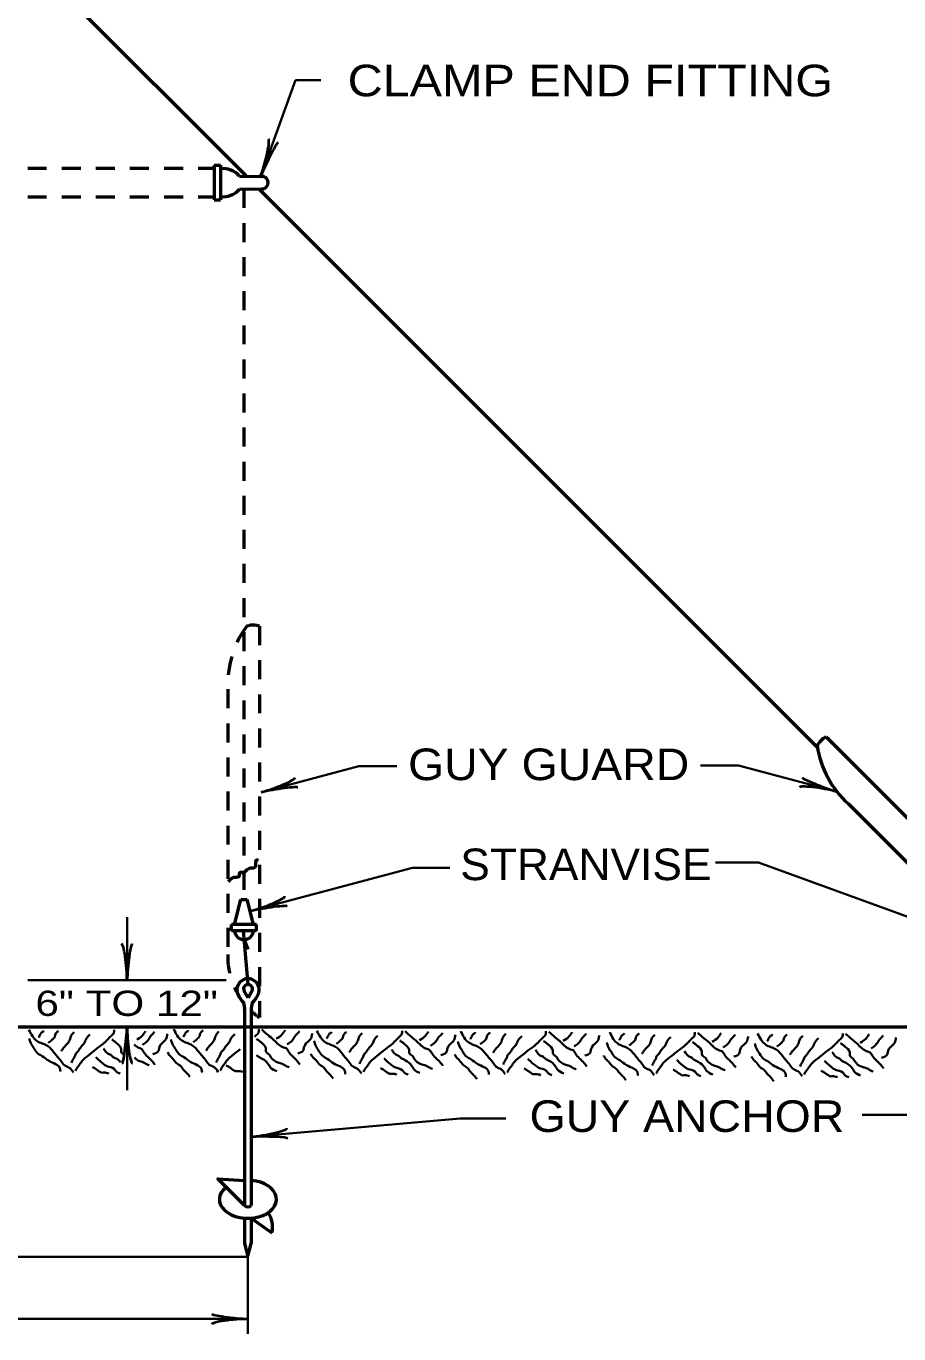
# Model space of a CAD drawing. Extents: x 12366 to 13046, y 9129 to 9570.
# Drawn here: x 12793.4 to 12862.5, y 9373.5 to 9477.1 of the extents above; entities that cross this region are included whole.
import ezdxf
from ezdxf.enums import TextEntityAlignment as Align

# ---------------------------------------------------------------- set-up
doc = ezdxf.new("R2010")
doc.units = 0
doc.linetypes.add('SHORT_DASHED', pattern=[2.7, 1.5, -1.2])
doc.layers.add('1', color=7, linetype='Continuous', lineweight=53)

msp = doc.modelspace()

# ---------------------------------------------------------------- linework, layer by layer
at = {"layer": '1'}
for p, q in [((12749.576, 9526.413), (12810.747, 9465.242)), ((12808.241, 9466.052), (12808.241, 9463.303)), ((12808.241, 9466.052), (12808.741, 9466.052)), ((12808.741, 9466.052), (12808.741, 9463.303)), ((12810.253, 9465.181), (12811.991, 9465.177)), ((12810.253, 9464.17), (12812.069, 9464.177)), ((12811.799, 9464.19), (12856.023, 9419.966)), ((12808.241, 9463.303), (12808.741, 9463.303)), ((12856.715, 9420.771), (12878.635, 9398.851)), ((12858.482, 9415.468), (12873.332, 9400.618)), ((12809.862, 9405.911), (12810.362, 9407.911)), ((12810.362, 9407.911), (12810.862, 9407.911)), ((12811.362, 9405.911), (12810.862, 9407.911)), ((12811.612, 9405.911), (12809.612, 9405.911)), ((12809.612, 9405.411), (12809.612, 9405.911)), ((12811.612, 9405.411), (12811.612, 9405.911)), ((12811.612, 9405.411), (12809.612, 9405.411)), ((12810.94, 9401.156), (12810.568, 9405.408)), ((12810.627, 9404.725), (12810.906, 9403.961)), ((12810.932, 9400.107), (12810.632, 9400.626)), ((12810.932, 9400.107), (12811.232, 9400.626)), ((12811.189, 9399.121), (12811.189, 9393.883)), ((12722.941, 9397.801), (12909.771, 9397.801)), ((12811.189, 9393.841), (12811.189, 9383.648)), ((12811.189, 9382.648), (12811.189, 9380.648)), ((12811.189, 9382.648), (12812.828, 9381.501))]:
    msp.add_line(p, q, dxfattribs=at)
at = {"layer": '1', "linetype": 'SHORT_DASHED'}
for p, q in [((12747.583, 9465.812), (12808.241, 9465.812)), ((12810.612, 9464.172), (12810.612, 9407.911)), ((12747.584, 9463.563), (12808.241, 9463.563)), ((12811.835, 9429.545), (12811.835, 9398.545)), ((12809.335, 9424.545), (12809.335, 9403.545))]:
    msp.add_line(p, q, dxfattribs=at)
at = {"layer": '1', "lineweight": 35}
for p, q in [((12819.718, 9418.465), (12811.99, 9416.394)), ((12819.718, 9418.465), (12822.718, 9418.465)), ((12849.776, 9418.521), (12846.776, 9418.521)), ((12857.504, 9416.451), (12849.776, 9418.521)), ((12823.949, 9410.414), (12811.165, 9406.989)), ((12823.949, 9410.414), (12826.928, 9410.414)), ((12851.357, 9410.834), (12847.966, 9410.834)), ((12871.535, 9403.49), (12851.357, 9410.834)), ((12801.351, 9401.504), (12801.351, 9406.504)), ((12809.21, 9401.504), (12793.491, 9401.504)), ((12801.351, 9397.801), (12801.351, 9392.801)), ((12827.73, 9390.549), (12811.189, 9389.102)), ((12827.73, 9390.549), (12831.352, 9390.549)), ((12863.862, 9390.849), (12859.568, 9390.849)), ((12810.907, 9379.6), (12791.754, 9379.6)), ((12810.922, 9379.562), (12810.922, 9373.495)), ((12747.004, 9374.68), (12810.943, 9374.68))]:
    msp.add_line(p, q, dxfattribs=at)
msp.add_lwpolyline([(12811.966, 9465.264), (12814.702, 9472.782), (12816.702, 9472.782)], dxfattribs=at)
at = {"layer": '1'}
for points in [[(12810.666, 9399.121), (12810.666, 9393.841), (12810.666, 9383.648)], [(12810.666, 9383.648), (12808.545, 9385.769), (12810.653, 9385.637)], [(12810.666, 9382.648), (12810.666, 9380.648), (12810.928, 9379.648), (12811.189, 9380.648)]]:
    msp.add_lwpolyline(points, dxfattribs=at)
for centre, radius, start, end in [((12808.958, 9464.097), 1.689, 39.94521, 97.50756), ((12812.03, 9464.677), 0.501, 265.53287, 94.46714), ((12808.958, 9465.255), 1.689, 262.49244, 320.05479), ((12857.397, 9419.381), 1.548, 116.15616, 153.84384), ((12863.657, 9421.219), 7.737, 188.58388, 228.01714), ((12810.612, 9405.479), 0.753, 185.20411, 354.79589), ((12810.933, 9400.734), 0.887, 337.37581, 202.62419), ((12810.932, 9400.807), 0.35, 328.9871, 211.0129), ((12812.574, 9401.633), 2.755, 206.74116, 223.96028), ((12809.203, 9399.242), 1.469, 355.24577, 19.00426), ((12812.653, 9399.242), 1.469, 160.99574, 184.75423), ((12809.675, 9401.384), 2.301, 313.69833, 334.49446), ((12810.928, 9383.929), 0.384, 227.04039, 312.95961), ((12810.789, 9381.953), 2.088, 347.48706, 33.42981)]:
    msp.add_arc(centre, radius, start, end, dxfattribs=at)
at = {"layer": '1', "linetype": 'SHORT_DASHED'}
for centre, radius, start, end in [((12817.061, 9424.952), 7.737, 143.58388, 183.01714), ((12811.335, 9428.08), 1.548, 71.15616, 108.84384), ((12815.16, 9403.333), 5.829, 177.90975, 209.56823), ((12815.16, 9403.333), 5.829, 227.0576, 235.22035)]:
    msp.add_arc(centre, radius, start, end, dxfattribs=at)
at = {"layer": '1', "lineweight": 40}
for centre, major_axis, ratio, start_param, end_param in [((12812.08, 9466.384), (-0.464, -1.731), 0.122415, 0.8963533, 3.1415927), ((12812.548, 9466.245), (0.766, 1.59), 0.07063, 6.2823074, 8.5597026), ((12812.973, 9416.943), (-1.684, -0.613), 0.122415, 0.8963533, 3.1415927), ((12856.476, 9416.945), (-1.651, 0.624), 0.07063, 6.2823074, 8.5597026), ((12813.127, 9416.48), (1.742, 0.285), 0.07063, 6.2823074, 8.5597026), ((12856.378, 9416.466), (1.765, -0.311), 0.122415, 0.8963533, 3.1415927), ((12812.148, 9407.538), (-1.684, -0.613), 0.122415, 0.8963533, 3.1415927), ((12812.302, 9407.074), (1.742, 0.285), 0.07063, 6.2823074, 8.5597026), ((12801.074, 9402.595), (0.156, -1.786), 0.122415, 0.8963533, 3.1415927), ((12801.562, 9402.625), (0.176, 1.756), 0.07063, 6.2823074, 8.5597026), ((12801.139, 9396.681), (-0.176, -1.756), 0.07063, 6.2823074, 8.5597026), ((12801.627, 9396.71), (-0.156, 1.786), 0.122415, 0.8963533, 3.1415927), ((12812.252, 9389.472), (-1.765, -0.311), 0.122415, 0.8963533, 3.1415927), ((12812.324, 9388.989), (1.765, -0.022), 0.07063, 6.2823074, 8.5597026), ((12809.823, 9374.891), (1.756, -0.176), 0.07063, 3.1407148, 5.41811), ((12809.852, 9374.403), (1.786, 0.156), 0.122415, 0.8963533, 3.1415927)]:
    msp.add_ellipse(centre, major_axis=major_axis, ratio=ratio, start_param=start_param, end_param=end_param, dxfattribs=at)
at = {"layer": '1'}
msp.add_ellipse((12810.928, 9384.148), major_axis=(-2.262, 0), ratio=0.663245, start_param=5.5824837, end_param=10.8796755, dxfattribs=at)
msp.add_spline([(12811.769, 9411), (12811.601, 9411.015), (12811.535, 9410.642), (12811.493, 9410.449), (12811.146, 9410.37), (12810.765, 9410.178), (12810.605, 9410.029), (12810.251, 9409.995), (12810.228, 9409.74), (12809.893, 9409.643), (12809.601, 9409.539), (12809.365, 9409.29)], degree=3, dxfattribs=at)
at = {"layer": '1', "lineweight": 35}
for points in [[(12793.581, 9397.583), (12794.221, 9396.688), (12795.053, 9396.304), (12795.564, 9395.792), (12795.82, 9395.472), (12796.14, 9395.088), (12796.396, 9394.768), (12796.78, 9394.576), (12797.1, 9394.192)], [(12800.331, 9397.583), (12800.331, 9397.456), (12800.267, 9397.263), (12800.139, 9397.136), (12800.011, 9397.008), (12799.755, 9396.752), (12799.563, 9396.56), (12798.987, 9396.112), (12798.667, 9395.856), (12798.027, 9395.344), (12797.771, 9395.088), (12797.644, 9394.896), (12797.452, 9394.64), (12797.26, 9394.32)], [(12805.049, 9397.625), (12805.689, 9396.729), (12806.521, 9396.345), (12807.032, 9395.833), (12807.288, 9395.513), (12807.608, 9395.129), (12807.864, 9394.81), (12808.248, 9394.618), (12808.568, 9394.234)], [(12811.799, 9397.625), (12811.799, 9397.497), (12811.735, 9397.305), (12811.607, 9397.177), (12811.479, 9397.049), (12811.459, 9397.029)], [(12812.023, 9397.593), (12812.534, 9397.145), (12812.982, 9396.761), (12813.75, 9396.185), (12813.942, 9396.121), (12814.134, 9395.865), (12814.454, 9395.481), (12814.838, 9395.097), (12815.03, 9394.842)], [(12793.605, 9396.9), (12793.733, 9396.516), (12793.988, 9396.1), (12794.308, 9395.684), (12794.628, 9395.492), (12795.172, 9395.108), (12796.036, 9394.532), (12796.068, 9394.277)], [(12794.733, 9397.512), (12794.637, 9397.384), (12794.605, 9397.384), (12794.541, 9397.32), (12794.381, 9397.032), (12794.349, 9396.968)], [(12795.916, 9397.48), (12795.724, 9397.32), (12795.66, 9397.16), (12795.596, 9396.968), (12795.468, 9396.84), (12795.404, 9396.776), (12795.116, 9396.552)], [(12797.164, 9397.384), (12796.972, 9397.192), (12796.844, 9396.872), (12796.684, 9396.552), (12796.332, 9396.168), (12796.204, 9395.976), (12796.14, 9395.88)], [(12798.411, 9397.192), (12798.123, 9396.872), (12797.963, 9396.52), (12797.708, 9396.232), (12797.516, 9395.944), (12797.324, 9395.72), (12797.228, 9395.496), (12797.1, 9395.272), (12796.94, 9394.953)], [(12800.139, 9396.808), (12800.331, 9396.68), (12800.523, 9396.52), (12800.874, 9396.072), (12800.906, 9395.784), (12801.081, 9395.632)], [(12802.119, 9396.799), (12802.567, 9397.119), (12802.663, 9397.246), (12802.823, 9397.47)], [(12802.57, 9396.392), (12802.922, 9396.648), (12803.146, 9396.968), (12803.21, 9397.064), (12803.338, 9397.192), (12803.53, 9397.416)], [(12803.402, 9395.656), (12803.85, 9395.912), (12803.913, 9396.2), (12804.329, 9396.712), (12804.457, 9396.872), (12804.521, 9397.128), (12804.553, 9397.256)], [(12804.825, 9396.817), (12804.953, 9396.433), (12805.209, 9396.017), (12805.529, 9395.602), (12805.849, 9395.41), (12806.392, 9395.026), (12807.256, 9394.45), (12807.288, 9394.194)], [(12806.201, 9397.553), (12806.105, 9397.425), (12806.073, 9397.425), (12806.009, 9397.361), (12805.849, 9397.073), (12805.817, 9397.009)], [(12807.384, 9397.521), (12807.192, 9397.361), (12807.128, 9397.201), (12807.064, 9397.009), (12806.936, 9396.881), (12806.872, 9396.817), (12806.584, 9396.593)], [(12808.632, 9397.425), (12808.44, 9397.233), (12808.312, 9396.913), (12808.152, 9396.593), (12807.8, 9396.209), (12807.672, 9396.017), (12807.608, 9395.922)], [(12809.879, 9397.233), (12809.591, 9396.913), (12809.431, 9396.561), (12809.176, 9396.273), (12808.984, 9395.985), (12808.792, 9395.762), (12808.696, 9395.538), (12808.568, 9395.314), (12808.408, 9394.994)], [(12811.607, 9396.849), (12811.799, 9396.721), (12811.991, 9396.561), (12812.342, 9396.113), (12812.374, 9395.826), (12812.63, 9395.602), (12812.726, 9395.442), (12813.366, 9394.962), (12813.75, 9394.834), (12813.846, 9394.77), (12814.198, 9394.61)], [(12813.174, 9396.881), (12813.622, 9397.201), (12813.718, 9397.329), (12813.878, 9397.553)], [(12814.038, 9396.433), (12814.39, 9396.689), (12814.614, 9397.009), (12814.678, 9397.105), (12814.806, 9397.233), (12814.998, 9397.457)], [(12814.87, 9395.698), (12815.317, 9395.953), (12815.381, 9396.241), (12815.797, 9396.753), (12815.925, 9396.913), (12815.989, 9397.169), (12816.021, 9397.297)], [(12816.169, 9396.693), (12816.297, 9396.31), (12816.553, 9395.894), (12816.873, 9395.478), (12817.193, 9395.286), (12817.737, 9394.902), (12818.601, 9394.326), (12818.632, 9394.07)], [(12816.393, 9397.501), (12817.033, 9396.605), (12817.865, 9396.221), (12818.377, 9395.709), (12818.632, 9395.39), (12818.952, 9395.006), (12819.208, 9394.686), (12819.592, 9394.494), (12819.912, 9394.11)], [(12817.545, 9397.429), (12817.449, 9397.301), (12817.417, 9397.301), (12817.353, 9397.237), (12817.193, 9396.949), (12817.161, 9396.885)], [(12818.728, 9397.397), (12818.537, 9397.237), (12818.472, 9397.077), (12818.408, 9396.885), (12818.281, 9396.757), (12818.217, 9396.693), (12817.929, 9396.469)], [(12819.976, 9397.301), (12819.784, 9397.109), (12819.656, 9396.789), (12819.496, 9396.47), (12819.144, 9396.086), (12819.016, 9395.894), (12818.952, 9395.798)], [(12821.224, 9397.109), (12820.936, 9396.789), (12820.776, 9396.438), (12820.52, 9396.15), (12820.328, 9395.862), (12820.136, 9395.638), (12820.04, 9395.414), (12819.912, 9395.19), (12819.752, 9394.87)], [(12823.143, 9397.501), (12823.143, 9397.373), (12823.079, 9397.181), (12822.951, 9397.053), (12822.823, 9396.925), (12822.567, 9396.669), (12822.375, 9396.477), (12821.799, 9396.029), (12821.479, 9395.773), (12820.84, 9395.262), (12820.584, 9395.006), (12820.456, 9394.814), (12820.264, 9394.558), (12820.072, 9394.238)], [(12822.951, 9396.725), (12823.143, 9396.597), (12823.335, 9396.438), (12823.687, 9395.99), (12823.719, 9395.702), (12823.975, 9395.478), (12824.071, 9395.318), (12824.71, 9394.838), (12825.094, 9394.71), (12825.19, 9394.646), (12825.542, 9394.486)], [(12823.367, 9397.469), (12823.879, 9397.021), (12824.326, 9396.637), (12825.094, 9396.061), (12825.286, 9395.997), (12825.478, 9395.742), (12825.798, 9395.358), (12826.182, 9394.974), (12826.374, 9394.718)], [(12824.519, 9396.757), (12824.966, 9397.077), (12825.062, 9397.205), (12825.222, 9397.429)], [(12825.382, 9396.31), (12825.734, 9396.565), (12825.958, 9396.885), (12826.022, 9396.981), (12826.15, 9397.109), (12826.342, 9397.333)], [(12826.214, 9395.574), (12826.662, 9395.83), (12826.726, 9396.118), (12827.142, 9396.629), (12827.27, 9396.789), (12827.333, 9397.045), (12827.365, 9397.173)], [(12827.555, 9396.652), (12827.683, 9396.268), (12827.939, 9395.852), (12828.259, 9395.437), (12828.578, 9395.245), (12829.122, 9394.861), (12829.986, 9394.285), (12830.018, 9394.029)], [(12827.779, 9397.46), (12828.419, 9396.564), (12829.25, 9396.18), (12829.762, 9395.668), (12830.018, 9395.348), (12830.338, 9394.965), (12830.594, 9394.645), (12830.978, 9394.453), (12831.298, 9394.069)], [(12828.93, 9397.388), (12828.834, 9397.26), (12828.802, 9397.26), (12828.738, 9397.196), (12828.578, 9396.908), (12828.547, 9396.844)], [(12830.114, 9397.356), (12829.922, 9397.196), (12829.858, 9397.036), (12829.794, 9396.844), (12829.666, 9396.716), (12829.602, 9396.652), (12829.314, 9396.428)], [(12831.361, 9397.26), (12831.17, 9397.068), (12831.042, 9396.748), (12830.882, 9396.428), (12830.53, 9396.044), (12830.402, 9395.852), (12830.338, 9395.757)], [(12832.609, 9397.068), (12832.321, 9396.748), (12832.161, 9396.396), (12831.905, 9396.108), (12831.713, 9395.82), (12831.521, 9395.597), (12831.425, 9395.373), (12831.297, 9395.149), (12831.138, 9394.829)], [(12834.528, 9397.46), (12834.528, 9397.332), (12834.464, 9397.14), (12834.336, 9397.012), (12834.208, 9396.884), (12833.953, 9396.628), (12833.761, 9396.436), (12833.185, 9395.988), (12832.865, 9395.732), (12832.225, 9395.22), (12831.969, 9394.965), (12831.841, 9394.773), (12831.649, 9394.517), (12831.458, 9394.197)], [(12834.336, 9396.684), (12834.528, 9396.556), (12834.72, 9396.396), (12835.072, 9395.948), (12835.104, 9395.661), (12835.36, 9395.437), (12835.456, 9395.277), (12836.096, 9394.797), (12836.48, 9394.669), (12836.576, 9394.605), (12836.928, 9394.445)], [(12834.752, 9397.428), (12835.264, 9396.98), (12835.712, 9396.596), (12836.48, 9396.02), (12836.672, 9395.956), (12836.864, 9395.7), (12837.183, 9395.316), (12837.567, 9394.932), (12837.759, 9394.677)], [(12835.904, 9396.716), (12836.352, 9397.036), (12836.448, 9397.164), (12836.608, 9397.388)], [(12836.768, 9396.268), (12837.12, 9396.524), (12837.343, 9396.844), (12837.407, 9396.94), (12837.535, 9397.068), (12837.727, 9397.292)], [(12837.599, 9395.533), (12838.047, 9395.789), (12838.111, 9396.076), (12838.527, 9396.588), (12838.655, 9396.748), (12838.719, 9397.004), (12838.751, 9397.132)], [(12839.353, 9396.57), (12839.481, 9396.186), (12839.737, 9395.77), (12840.057, 9395.354), (12840.377, 9395.162), (12840.92, 9394.778), (12841.784, 9394.202), (12841.816, 9393.947)], [(12839.577, 9397.377), (12840.217, 9396.481), (12841.048, 9396.098), (12841.56, 9395.586), (12841.816, 9395.266), (12842.136, 9394.882), (12842.392, 9394.562), (12842.776, 9394.37), (12843.096, 9393.986)], [(12840.728, 9397.306), (12840.632, 9397.177), (12840.6, 9397.177), (12840.537, 9397.113), (12840.377, 9396.826), (12840.345, 9396.762)], [(12841.912, 9397.273), (12841.72, 9397.113), (12841.656, 9396.954), (12841.592, 9396.762), (12841.464, 9396.634), (12841.4, 9396.57), (12841.112, 9396.346)], [(12843.16, 9397.178), (12842.968, 9396.986), (12842.84, 9396.666), (12842.68, 9396.346), (12842.328, 9395.962), (12842.2, 9395.77), (12842.136, 9395.674)], [(12844.407, 9396.986), (12844.119, 9396.666), (12843.959, 9396.314), (12843.703, 9396.026), (12843.511, 9395.738), (12843.319, 9395.514), (12843.224, 9395.29), (12843.096, 9395.066), (12842.936, 9394.746)], [(12846.326, 9397.377), (12846.326, 9397.249), (12846.262, 9397.057), (12846.135, 9396.929), (12846.007, 9396.801), (12845.751, 9396.545), (12845.559, 9396.353), (12844.983, 9395.906), (12844.663, 9395.65), (12844.023, 9395.138), (12843.767, 9394.882), (12843.639, 9394.69), (12843.448, 9394.434), (12843.256, 9394.114)], [(12846.135, 9396.602), (12846.326, 9396.474), (12846.518, 9396.314), (12846.87, 9395.866), (12846.902, 9395.578), (12847.158, 9395.354), (12847.254, 9395.194), (12847.894, 9394.714), (12848.278, 9394.586), (12848.374, 9394.522), (12848.726, 9394.362)], [(12846.55, 9397.345), (12847.062, 9396.897), (12847.51, 9396.513), (12848.278, 9395.938), (12848.47, 9395.874), (12848.662, 9395.618), (12848.982, 9395.234), (12849.365, 9394.85), (12849.557, 9394.594)], [(12847.702, 9396.634), (12848.15, 9396.954), (12848.246, 9397.082), (12848.406, 9397.306)], [(12848.566, 9396.186), (12848.918, 9396.442), (12849.142, 9396.762), (12849.206, 9396.858), (12849.333, 9396.986), (12849.525, 9397.209)], [(12849.397, 9395.45), (12849.845, 9395.706), (12849.909, 9395.994), (12850.325, 9396.506), (12850.453, 9396.666), (12850.517, 9396.922), (12850.549, 9397.05)], [(12851.292, 9397.295), (12851.932, 9396.399), (12852.764, 9396.015), (12853.276, 9395.503), (12853.532, 9395.183), (12853.852, 9394.799), (12854.108, 9394.48), (12854.491, 9394.288), (12854.811, 9393.904)], [(12852.444, 9397.223), (12852.348, 9397.095), (12852.316, 9397.095), (12852.252, 9397.031), (12852.092, 9396.743), (12852.06, 9396.679)], [(12853.628, 9397.191), (12853.436, 9397.031), (12853.372, 9396.871), (12853.308, 9396.679), (12853.18, 9396.551), (12853.116, 9396.487), (12852.828, 9396.263)], [(12854.875, 9397.095), (12854.683, 9396.903), (12854.555, 9396.583), (12854.395, 9396.263), (12854.043, 9395.879), (12853.915, 9395.688), (12853.851, 9395.592)], [(12856.123, 9396.903), (12855.835, 9396.583), (12855.675, 9396.231), (12855.419, 9395.943), (12855.227, 9395.655), (12855.035, 9395.432), (12854.939, 9395.208), (12854.811, 9394.984), (12854.651, 9394.664)], [(12858.042, 9397.295), (12858.042, 9397.167), (12857.978, 9396.975), (12857.85, 9396.847), (12857.722, 9396.719), (12857.466, 9396.463), (12857.274, 9396.271), (12856.699, 9395.823), (12856.379, 9395.567), (12855.739, 9395.055), (12855.483, 9394.799), (12855.355, 9394.608), (12855.163, 9394.352), (12854.971, 9394.032)], [(12858.266, 9397.263), (12858.778, 9396.815), (12859.226, 9396.431), (12859.993, 9395.855), (12860.185, 9395.791), (12860.377, 9395.535), (12860.697, 9395.151), (12861.081, 9394.767), (12861.273, 9394.512)], [(12859.418, 9396.551), (12859.865, 9396.871), (12859.961, 9396.999), (12860.121, 9397.223)], [(12860.281, 9396.103), (12860.633, 9396.359), (12860.857, 9396.679), (12860.921, 9396.775), (12861.049, 9396.903), (12861.241, 9397.127)], [(12861.113, 9395.368), (12861.561, 9395.623), (12861.625, 9395.911), (12862.041, 9396.423), (12862.169, 9396.583), (12862.233, 9396.839), (12862.265, 9396.967)], [(12799.499, 9396.104), (12799.979, 9395.624), (12800.075, 9395.592), (12800.171, 9395.496), (12800.587, 9395.24), (12800.842, 9395.017)], [(12801.919, 9396.416), (12802.282, 9396.144), (12802.474, 9396.08), (12802.666, 9395.824), (12802.986, 9395.44), (12803.37, 9395.056), (12803.562, 9394.8)], [(12804.569, 9395.794), (12804.697, 9395.57), (12804.953, 9395.314), (12805.273, 9394.93), (12805.561, 9394.738), (12805.817, 9394.418), (12806.073, 9394.162), (12806.328, 9393.842)], [(12810.323, 9396.048), (12810.135, 9395.897), (12809.495, 9395.385), (12809.239, 9395.129), (12809.112, 9394.938), (12808.92, 9394.682), (12808.728, 9394.362)], [(12811.617, 9395.559), (12811.639, 9395.538), (12812.055, 9395.282), (12812.566, 9394.834), (12812.726, 9394.578), (12813.206, 9394.29)], [(12815.913, 9395.67), (12816.041, 9395.446), (12816.297, 9395.19), (12816.617, 9394.806), (12816.905, 9394.614), (12817.161, 9394.294), (12817.417, 9394.038), (12817.673, 9393.718)], [(12822.311, 9396.022), (12822.791, 9395.542), (12822.887, 9395.51), (12822.983, 9395.414), (12823.399, 9395.158), (12823.911, 9394.71), (12824.071, 9394.454), (12824.55, 9394.166)], [(12827.299, 9395.629), (12827.427, 9395.405), (12827.683, 9395.149), (12828.003, 9394.765), (12828.291, 9394.573), (12828.547, 9394.253), (12828.802, 9393.997), (12829.058, 9393.677)], [(12833.697, 9395.98), (12834.177, 9395.501), (12834.272, 9395.469), (12834.368, 9395.373), (12834.784, 9395.117), (12835.296, 9394.669), (12835.456, 9394.413), (12835.936, 9394.125)], [(12839.097, 9395.546), (12839.225, 9395.322), (12839.481, 9395.066), (12839.801, 9394.682), (12840.089, 9394.49), (12840.345, 9394.171), (12840.6, 9393.915), (12840.856, 9393.595)], [(12845.495, 9395.898), (12845.975, 9395.418), (12846.071, 9395.386), (12846.167, 9395.29), (12846.582, 9395.034), (12847.094, 9394.586), (12847.254, 9394.331), (12847.734, 9394.043)], [(12851.068, 9396.487), (12851.196, 9396.103), (12851.452, 9395.688), (12851.772, 9395.272), (12852.092, 9395.08), (12852.636, 9394.696), (12853.5, 9394.12), (12853.532, 9393.864)], [(12857.21, 9395.815), (12857.69, 9395.336), (12857.786, 9395.304), (12857.882, 9395.208), (12858.298, 9394.952), (12858.81, 9394.504), (12858.97, 9394.248), (12859.45, 9393.96)], [(12857.85, 9396.519), (12858.042, 9396.391), (12858.234, 9396.231), (12858.586, 9395.783), (12858.618, 9395.496), (12858.874, 9395.272), (12858.97, 9395.112), (12859.61, 9394.632), (12859.993, 9394.504), (12860.089, 9394.44), (12860.441, 9394.28)], [(12798.603, 9394.633), (12798.827, 9394.505), (12799.243, 9394.217), (12799.307, 9394.185), (12799.499, 9394.185), (12799.915, 9394.121)], [(12798.891, 9395.4), (12799.307, 9395.017), (12799.467, 9394.889), (12799.755, 9394.697), (12800.331, 9394.473), (12800.523, 9394.249), (12800.81, 9394.121)], [(12801.935, 9395.378), (12802.27, 9395.127), (12802.653, 9394.999), (12802.749, 9394.935), (12803.101, 9394.775)], [(12809.205, 9394.756), (12809.429, 9394.628), (12809.845, 9394.341), (12809.909, 9394.309), (12810.101, 9394.309), (12810.516, 9394.245)], [(12821.415, 9394.55), (12821.639, 9394.422), (12822.055, 9394.134), (12822.119, 9394.102), (12822.311, 9394.102), (12822.727, 9394.038)], [(12821.703, 9395.318), (12822.119, 9394.934), (12822.279, 9394.806), (12822.567, 9394.614), (12823.143, 9394.39), (12823.335, 9394.166), (12823.623, 9394.038)], [(12832.801, 9394.509), (12833.025, 9394.381), (12833.441, 9394.093), (12833.505, 9394.061), (12833.697, 9394.061), (12834.113, 9393.997)], [(12833.089, 9395.277), (12833.505, 9394.893), (12833.665, 9394.765), (12833.953, 9394.573), (12834.528, 9394.349), (12834.72, 9394.125), (12835.008, 9393.997)], [(12844.887, 9395.194), (12845.303, 9394.81), (12845.463, 9394.682), (12845.751, 9394.49), (12846.326, 9394.266), (12846.518, 9394.043), (12846.806, 9393.915)], [(12850.813, 9395.464), (12850.94, 9395.24), (12851.196, 9394.984), (12851.516, 9394.6), (12851.804, 9394.408), (12852.06, 9394.088), (12852.316, 9393.832), (12852.572, 9393.512)], [(12856.603, 9395.112), (12857.018, 9394.728), (12857.178, 9394.6), (12857.466, 9394.408), (12858.042, 9394.184), (12858.234, 9393.96), (12858.522, 9393.832)], [(12844.599, 9394.426), (12844.823, 9394.298), (12845.239, 9394.011), (12845.303, 9393.979), (12845.495, 9393.979), (12845.911, 9393.915)], [(12856.315, 9394.344), (12856.539, 9394.216), (12856.954, 9393.928), (12857.018, 9393.896), (12857.21, 9393.896), (12857.626, 9393.832)]]:
    msp.add_spline(points, degree=3, dxfattribs=at)

# ---------------------------------------------------------------- texts
at = {"layer": '1'}
for s, width, p in [('CLAMP END FITTING', 1.15, (12818.822, 9471.517)), ('STRANVISE', 1.05, (12827.744, 9409.431))]:
    msp.add_text(s, height=2.5, dxfattribs=dict(at, width=width)).set_placement(p)
for s, height, width, p in [('GUY GUARD', 2.5, 1.1, (12834.745, 9417.354)), ('6" TO 12"', 2, 1.25, (12801.32, 9398.677)), ('GUY ANCHOR', 2.5, 1.1, (12845.696, 9389.486))]:
    msp.add_text(s, height=height, dxfattribs=dict(at, width=width)).set_placement(p, align=Align.CENTER)

doc.saveas('drawing.dxf')
